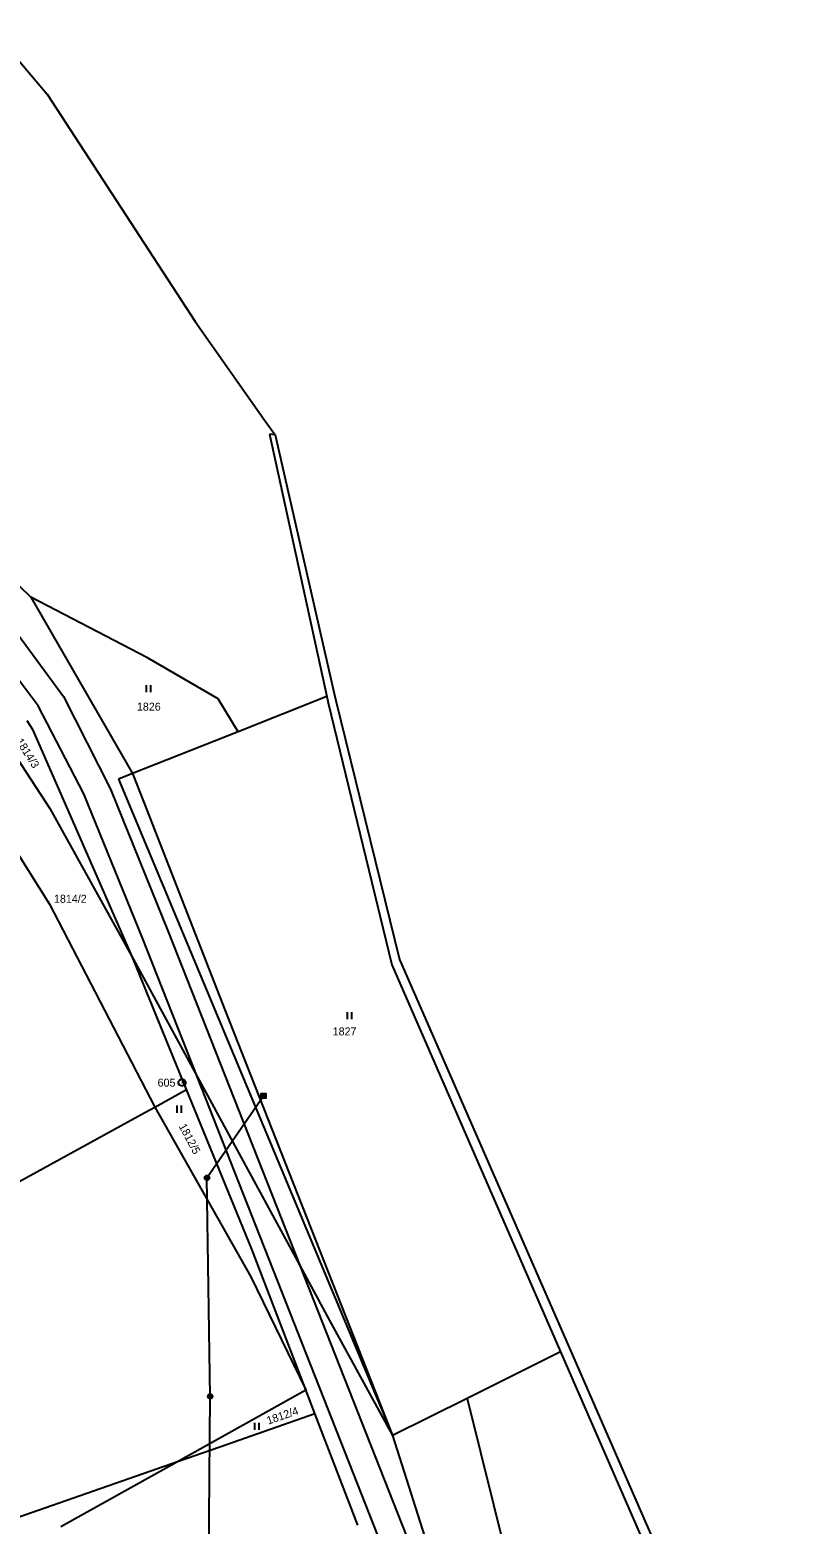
# Model space of a CAD drawing. Extents: x -609861 to -605046, y -1120287 to -1116307.
# Drawn here: x -608869.6 to -608704.8, y -1116873.3 to -1116555.9 of the extents above; entities that cross this region are included whole.
import ezdxf

# ---------------------------------------------------------------- set-up
doc = ezdxf.new("R2010")
doc.units = 0
for name, color, linetype in [('Vrstva 1', 7, 'Continuous'), ('Vrstva 2', 7, 'Continuous'), ('Vrstva 3', 7, 'Continuous'), ('Vrstva 4', 7, 'Continuous'), ('Vrstva 6', 7, 'Continuous'), ('Vrstva 8', 7, 'Continuous')]:
    doc.layers.add(name, color=color, linetype=linetype)

msp = doc.modelspace()

# ---------------------------------------------------------------- linework, layer by layer
at = {"layer": 'Vrstva 1'}
for p, q in [((-608877.57, -1116555.93), (-608866, -1116569.59)), ((-608866, -1116569.59), (-608834.57, -1116617.84)), ((-608941.31, -1116606.69), (-608869.47, -1116676.41)), ((-608834.57, -1116617.84), (-608819.57, -1116639.08)), ((-608819.57, -1116639.08), (-608817.58, -1116641.91)), ((-608817.58, -1116641.91), (-608818.78, -1116641.82)), ((-608818.78, -1116641.82), (-608806.6, -1116697.51)), ((-608817.58, -1116641.91), (-608804.99, -1116696.87)), ((-608869.47, -1116676.41), (-608847.84, -1116713.85)), ((-608844.66, -1116689.32), (-608869.47, -1116676.41)), ((-608829.65, -1116698), (-608844.66, -1116689.32)), ((-608825.44, -1116704.97), (-608829.65, -1116698)), ((-608806.6, -1116697.51), (-608825.44, -1116704.97)), ((-608806.6, -1116697.51), (-608806.31, -1116698.82)), ((-608804.99, -1116696.87), (-608804.64, -1116698.38)), ((-608804.64, -1116698.38), (-608791.15, -1116753.35)), ((-608806.31, -1116698.82), (-608792.76, -1116754.45)), ((-608868.95, -1116704.65), (-608870.21, -1116702.68)), ((-608847.71, -1116753.22), (-608868.95, -1116704.65)), ((-608875.59, -1116705.66), (-608865.39, -1116721.3)), ((-608825.44, -1116704.97), (-608847.84, -1116713.85)), ((-608884.84, -1116710.8), (-608865.51, -1116741.58)), ((-608847.84, -1116713.85), (-608845.39, -1116720.13)), ((-608845.39, -1116720.13), (-608828.22, -1116764.06)), ((-608865.39, -1116721.3), (-608847.71, -1116753.22)), ((-608865.51, -1116741.58), (-608843.14, -1116784.71)), ((-608847.71, -1116753.22), (-608834.12, -1116778.22)), ((-608836.35, -1116780.99), (-608847.71, -1116753.22)), ((-608792.76, -1116754.45), (-608756.94, -1116836.66)), ((-608791.15, -1116753.35), (-608755.13, -1116835.76)), ((-608828.22, -1116764.06), (-608792.64, -1116854.47)), ((-608834.12, -1116778.22), (-608812.32, -1116818.33)), ((-608843.14, -1116784.71), (-608836.35, -1116780.99)), ((-608822.5, -1116814.83), (-608836.35, -1116780.99)), ((-608939.88, -1116837.71), (-608845.21, -1116785.85)), ((-608845.21, -1116785.85), (-608843.14, -1116784.71)), ((-608843.14, -1116784.71), (-608822.75, -1116820.77)), ((-608811.01, -1116844.77), (-608822.5, -1116814.83)), ((-608812.32, -1116818.33), (-608805.98, -1116829.99)), ((-608822.75, -1116820.77), (-608811.01, -1116844.77)), ((-608805.98, -1116829.99), (-608792.64, -1116854.47)), ((-608756.94, -1116836.66), (-608776.76, -1116846.55)), ((-608756.94, -1116836.66), (-608723.86, -1116912.58)), ((-608755.13, -1116835.76), (-608704.77, -1116950.96)), ((-608838.32, -1116859.96), (-608811.01, -1116844.77)), ((-608809.1, -1116849.76), (-608811.01, -1116844.77)), ((-608776.76, -1116846.55), (-608792.64, -1116854.47)), ((-608776.76, -1116846.55), (-608757.6, -1116924.02)), ((-608829.32, -1116856.82), (-608809.1, -1116849.76)), ((-608799.99, -1116873.49), (-608809.1, -1116849.76)), ((-608838.32, -1116859.96), (-608829.32, -1116856.82)), ((-608792.64, -1116854.47), (-608779.46, -1116895.79)), ((-608908.69, -1116884.53), (-608838.32, -1116859.96)), ((-608863.09, -1116873.74), (-608838.32, -1116859.96))]:
    msp.add_line(p, q, dxfattribs=at)
at = {"layer": 'Vrstva 3'}
for p, q in [((-608844.93, -1116695.06), (-608844.93, -1116696.56)), ((-608843.93, -1116696.56), (-608843.93, -1116695.06)), ((-608802.23, -1116764.55), (-608802.23, -1116766.05)), ((-608801.23, -1116766.05), (-608801.23, -1116764.55)), ((-608838.41, -1116784.39), (-608838.41, -1116785.89)), ((-608837.41, -1116785.89), (-608837.41, -1116784.39)), ((-608821.96, -1116851.75), (-608821.96, -1116853.25)), ((-608820.96, -1116853.25), (-608820.96, -1116851.75))]:
    msp.add_line(p, q, dxfattribs=at)
at = {"layer": 'Vrstva 4'}
for p, q in [((-608873.87, -1116682.09), (-608862.5, -1116697.52)), ((-608867.91, -1116699.46), (-608878.8, -1116684.95)), ((-608862.5, -1116697.52), (-608852.56, -1116717.21)), ((-608858.19, -1116718.15), (-608867.91, -1116699.46)), ((-608847.84, -1116713.85), (-608850.85, -1116715.04)), ((-608852.56, -1116717.21), (-608840.22, -1116747.62)), ((-608850.85, -1116715.04), (-608792.64, -1116854.47)), ((-608845.66, -1116748.96), (-608858.19, -1116718.15)), ((-608834.12, -1116778.22), (-608845.66, -1116748.96)), ((-608840.22, -1116747.62), (-608812.32, -1116818.33)), ((-608721.43, -1117063.98), (-608834.12, -1116778.22)), ((-608812.32, -1116818.33), (-608715.82, -1117062.88))]:
    msp.add_line(p, q, dxfattribs=at)
at = {"layer": 'Vrstva 6'}
for p, q in [((-608832.04, -1116799.72), (-608820.04, -1116782.3)), ((-608831.36, -1116846.15), (-608832.04, -1116799.72)), ((-608831.73, -1116894.21), (-608831.36, -1116846.15))]:
    msp.add_line(p, q, dxfattribs=at)
for points in [[(-608820.54, -1116781.8), (-608819.54, -1116781.8), (-608819.54, -1116782.8), (-608820.54, -1116782.8), (-608820.54, -1116781.8), (-608820.48, -1116781.86), (-608819.6, -1116781.86), (-608819.6, -1116781.94), (-608820.48, -1116781.94), (-608820.48, -1116782.02), (-608819.6, -1116782.02), (-608819.6, -1116782.1), (-608820.48, -1116782.1), (-608820.48, -1116782.18), (-608819.6, -1116782.18), (-608819.6, -1116782.26), (-608820.48, -1116782.26), (-608820.48, -1116782.34), (-608819.6, -1116782.34), (-608819.6, -1116782.42), (-608820.48, -1116782.42), (-608820.48, -1116782.5), (-608819.6, -1116782.5), (-608819.6, -1116782.58), (-608820.48, -1116782.58), (-608820.48, -1116782.66), (-608819.6, -1116782.66), (-608819.6, -1116782.74), (-608820.48, -1116782.74)], [(-608832.19, -1116799.24), (-608831.88, -1116799.24), (-608831.63, -1116799.42), (-608831.53, -1116799.71), (-608831.63, -1116800), (-608831.88, -1116800.18), (-608832.19, -1116800.18), (-608832.44, -1116800), (-608832.54, -1116799.71), (-608832.44, -1116799.42), (-608832.19, -1116799.24), (-608832.16, -1116799.28), (-608831.92, -1116799.28), (-608831.76, -1116799.36), (-608832.32, -1116799.36), (-608832.4, -1116799.44), (-608831.68, -1116799.44), (-608831.68, -1116799.52), (-608832.4, -1116799.52), (-608832.44, -1116799.6), (-608831.64, -1116799.6), (-608831.6, -1116799.68), (-608832.48, -1116799.68), (-608832.48, -1116799.76), (-608831.6, -1116799.76), (-608831.63, -1116799.84), (-608832.44, -1116799.84), (-608832.43, -1116799.92), (-608831.62, -1116799.92), (-608831.67, -1116800), (-608832.39, -1116800), (-608832.31, -1116800.08), (-608831.75, -1116800.08), (-608831.86, -1116800.16), (-608832.2, -1116800.16)], [(-608831.51, -1116845.67), (-608831.2, -1116845.67), (-608830.95, -1116845.85), (-608830.85, -1116846.14), (-608830.95, -1116846.43), (-608831.2, -1116846.61), (-608831.51, -1116846.61), (-608831.76, -1116846.43), (-608831.86, -1116846.14), (-608831.76, -1116845.85), (-608831.51, -1116845.67), (-608831.48, -1116845.71), (-608831.24, -1116845.71), (-608831.08, -1116845.79), (-608831.64, -1116845.79), (-608831.72, -1116845.87), (-608831, -1116845.87), (-608831, -1116845.95), (-608831.72, -1116845.95), (-608831.76, -1116846.03), (-608830.96, -1116846.03), (-608830.92, -1116846.11), (-608831.8, -1116846.11), (-608831.8, -1116846.19), (-608830.92, -1116846.19), (-608830.95, -1116846.27), (-608831.76, -1116846.27), (-608831.75, -1116846.35), (-608830.94, -1116846.35), (-608830.99, -1116846.43), (-608831.71, -1116846.43), (-608831.63, -1116846.51), (-608831.07, -1116846.51), (-608831.18, -1116846.59), (-608831.52, -1116846.59)]]:
    msp.add_lwpolyline(points, dxfattribs=at)
at = {"layer": 'Vrstva 8'}
msp.add_line((-608837.39, -1116779.47), (-608837.29, -1116779.47), dxfattribs=at)
msp.add_lwpolyline([(-608837.15, -1116778.75), (-608836.81, -1116778.94), (-608836.62, -1116779.28), (-608836.62, -1116779.67), (-608836.81, -1116780.01), (-608837.15, -1116780.2), (-608837.54, -1116780.2), (-608837.88, -1116780.01), (-608838.07, -1116779.67), (-608838.07, -1116779.28), (-608837.88, -1116778.94), (-608837.54, -1116778.75)], close=True, dxfattribs=at)

# ---------------------------------------------------------------- texts
at = {"layer": 'Vrstva 2'}
for s, p in [('1826', (-608846.917, -1116700.51)), ('1814/2', (-608864.537, -1116741.3)), ('1827', (-608805.337, -1116769.47))]:
    msp.add_text(s, height=1.7, dxfattribs=at).set_placement(p)
for s, rotation, p in [('1814/3', 302.40713, (-608872.69, -1116707.032)), ('1812/5', 297.88076, (-608838.066, -1116788.747)), ('1812/4', 18.90761, (-608819.018, -1116852.133))]:
    msp.add_text(s, height=1.7, rotation=rotation, dxfattribs=at).set_placement(p)
at = {"layer": 'Vrstva 8'}
msp.add_text('605', height=1.7, dxfattribs=at).set_placement((-608842.523, -1116780.35))

doc.saveas('drawing.dxf')
